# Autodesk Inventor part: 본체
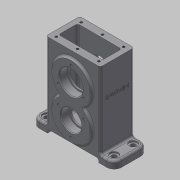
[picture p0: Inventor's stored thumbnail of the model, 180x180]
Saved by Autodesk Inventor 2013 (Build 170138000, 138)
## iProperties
Created: 2020-03
Part Number: 본체
Material: 일반
Document SubType Name: Modeling
Designer: mduedu
Density: 1 g/cm^3
Author: mduedu
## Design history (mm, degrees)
sketch "스케치1"
  geometry: L1 (-56, 0)-(56, 0); L2 (56, 0)-(56, 10); L3 (-56, 10)-(-56, 0); L4 (37, 10)-(37, 114); L5 (37, 114)-(-37, 114); L6 (-37, 114)-(-37, 10); L7 (56, 10)-(37, 10); L8 (-37, 10)-(-56, 10); L9 (0, 0)-(0, 114); 1 further point
  constraints: 18 end point, 5 parallel, 2 midpoint, 2 vertical, 1 coincident, 1 horizontal, 1 perpendicular
  dimensions: "d0" = 112 distance of L1.start L1.end; "d2" = 10 distance of L1.end L2.end; "d3" = 114 distance between parallel lines of L5 L1; "d4" = 74 distance between parallel lines of L4 L6
extrude "돌출1" new body sketch "스케치1" stored distance "d5" = 46; taper "d6" = 0 deg
sketch "스케치2"
  geometry: L1 (56, 0)-(-56, 0) reference; C1 r 26 at (0, 34); C2 r 26 at (0, 79); 1 further point
  constraints: 2 centre point, 2 vertical alignment, 1 equal radius
  dimensions: "d7" = 52 diameter of C2; "d9" = 34 distance from line of C1.centre L1; "d10" = 45 distance of C2.centre C1.centre
extrude "돌출2" join sketch "스케치2" stored distance "d11" = 52; taper "d12" = 0 deg
fillet "모깎기1" dims "d13" = 3
fillet "모깎기2" dims "d14" = 3
fillet "모깎기3" dims "d15" = 10
fillet "모깎기4" dims "d16" = 3
fillet "모깎기5" dims "d17" = 3
sketch "스케치3"
  geometry: L1 (-30, 114)-(30, 114); L2 (30, 114)-(30, 13); L3 (30, 13)-(-30, 13); L4 (-30, 13)-(-30, 114); L5 (-34, 114)-(34, 114) reference; L6 (46, 0)-(-46, 0) reference; 2 further points
  constraints: 8 end point, 2 parallel, 1 collinear, 1 horizontal, 1 midpoint, 1 perpendicular, 1 vertical alignment
  dimensions: "d18" = 60 distance between parallel lines of L2 L4; "d20" = 13 distance between parallel lines of L3 L6
extrude "돌출3" cut sketch "스케치3" stored distance "d21" = 26; taper "d22" = 0 deg
fillet "모깎기6" dims "d23" = 3
fillet "모깎기7" dims "d24" = 3
sketch "스케치4"
  geometry: L1 (-35, 0)-(35, 0); L2 (35, 0)-(35, 5); L3 (35, 5)-(-35, 5); L4 (-35, 5)-(-35, 0); 2 further points
  constraints: 8 end point, 2 parallel, 1 coincident, 1 horizontal, 1 midpoint, 1 perpendicular
  dimensions: "d25" = 70 distance of L1.start L1.end; "d27" = 5 distance of L1.end L2.end
extrude "돌출4" cut sketch "스케치4" stored distance "d28" = 26; taper "d29" = 0 deg
fillet "모깎기8" dims "d30" = 3
sketch "스케치5"
  geometry: A1 r 10 centre (-86, 33) between (-86, 43) and (-96, 33) reference; A2 r 10 centre (-86, 7) between (-96, 7) and (-86, -3) reference; A3 r 10 centre (6, 7) between (6, -3) and (16, 7) reference; A4 r 10 centre (6, 33) between (16, 33) and (6, 43) reference; 5 further points
  constraints: 4 coincident
hole "구멍1" sketch "스케치5" at (-86, 33), (-86, 7), (6, 7), (6, 33) diameter "d31" = 6.6; stored, may be unused: countersink angle "d35" = 90 deg, drill point angle "d37" = 118 deg; dims "d32" = 6, "d33" = 11, "d34" = 2, "d36" = 8
sketch "스케치6"
  geometry: A1 r 26 centre (0, 34) between (-16.403, 54.172) and (16.403, 54.172) reference; A2 r 3 centre (18.296, 56.5) between (16.403, 58.828) and (16.403, 54.172) reference; A3 r 26 centre (0, 79) between (16.403, 58.828) and (-16.403, 58.828) reference; A4 r 3 centre (-18.296, 56.5) between (-16.403, 54.172) and (-16.403, 58.828) reference; 2 further points
  constraints: 1 coincident
hole "구멍2" sketch "스케치6" at (0, 79) diameter "d38" = 28; stored, may be unused: countersink angle "d42" = 90 deg, drill point angle "d44" = 118 deg; dims "d39" = 6, "d40" = 32, "d41" = 11, "d43" = 8
sketch "스케치7"
  geometry: C1 r 16 at (0, 79) reference; A1 r 26 centre (0, 34) between (-16.403, 54.172) and (16.403, 54.172) reference; A2 r 3 centre (18.296, 56.5) between (16.403, 58.828) and (16.403, 54.172) reference; A3 r 26 centre (0, 79) between (16.403, 58.828) and (-16.403, 58.828) reference; A4 r 3 centre (-18.296, 56.5) between (-16.403, 54.172) and (-16.403, 58.828) reference; 2 further points
  constraints: 1 coincident
hole "구멍3" sketch "스케치7" at (0, 34) diameter "d45" = 24; stored, may be unused: countersink angle "d49" = 90 deg, drill point angle "d51" = 118 deg; dims "d46" = 6, "d47" = 28, "d48" = 11, "d50" = 8
sketch "스케치8"
  geometry: C1 r 14 at (0, 34) reference; A1 r 26 centre (0, 34) between (-16.403, 54.172) and (16.403, 54.172) reference; A2 r 3 centre (18.296, 56.5) between (16.403, 58.828) and (16.403, 54.172) reference; A3 r 26 centre (0, 79) between (16.403, 58.828) and (-16.403, 58.828) reference; A4 r 3 centre (-18.296, 56.5) between (-16.403, 54.172) and (-16.403, 58.828) reference; 2 further points
  constraints: 1 coincident
hole "구멍4" sketch "스케치8" at (0, 79) diameter "d52" = 24; stored, may be unused: countersink angle "d56" = 90 deg, drill point angle "d58" = 118 deg; dims "d53" = 6, "d54" = 28, "d55" = 11, "d57" = 8
sketch "스케치9" dims "d59" = 40
  geometry: C1 r 14 at (0, 34) reference; C2 r 16 at (0, 79) reference; A1 r 26 centre (0, 34) between (-16.403, 54.172) and (16.403, 54.172) reference; A2 r 3 centre (18.296, 56.5) between (16.403, 58.828) and (16.403, 54.172) reference; A3 r 26 centre (0, 79) between (16.403, 58.828) and (-16.403, 58.828) reference; A4 r 3 centre (-18.296, 56.5) between (-16.403, 54.172) and (-16.403, 58.828) reference; 3 further points
  constraints: 2 vertical alignment, 1 coincident, 2 other
hole "구멍5" sketch "스케치9" at (0, 99) diameter "d61" = 3.242; stored, may be unused: countersink angle "d65" = 90 deg, drill point angle "d67" = 118 deg; dims "d62" = 8, "d63" = 28, "d64" = 11, "d66" = 10
sketch "스케치10" dims "d71" = 40
  geometry: C1 r 1.621 at (17.321, 69) reference; C2 r 1.621 at (-17.321, 69) reference; C3 r 1.621 at (0, 99) reference; C4 r 14 at (0, 34) reference; C5 r 16 at (0, 79) reference; A1 r 26 centre (0, 34) between (-16.403, 54.172) and (16.403, 54.172) reference; A2 r 3 centre (18.296, 56.5) between (16.403, 58.828) and (16.403, 54.172) reference; A3 r 26 centre (0, 79) between (16.403, 58.828) and (-16.403, 58.828) reference; A4 r 3 centre (-18.296, 56.5) between (-16.403, 54.172) and (-16.403, 58.828) reference; 3 further points
  constraints: 2 vertical alignment, 1 coincident, 2 other
hole "구멍6" sketch "스케치10" at (0, 14) diameter "d72" = 3.242; stored, may be unused: countersink angle "d76" = 90 deg, drill point angle "d78" = 118 deg; dims "d73" = 8, "d74" = 28, "d75" = 11, "d77" = 10
sketch "스케치11"
  geometry: L1 (5, 6)-(63, 6); L2 (63, 6)-(63, 40); L3 (63, 40)-(5, 40); L4 (5, 40)-(5, 6); L5 (5, 6)-(63, 40); L6 (63, 6)-(5, 40); 7 further points
  constraints: 12 end point, 4 coincident, 4 midpoint, 2 parallel, 1 horizontal, 1 perpendicular
  dimensions: "d82" = 58 distance of L3.end L2.end; "d83" = 34 distance of L2.end L1.end
hole "구멍7" sketch "스케치11" at (5, 40), (63, 40), (63, 6), (5, 6), (34, 6), (34, 40) diameter "d84" = 3.242; stored, may be unused: countersink angle "d88" = 90 deg, drill point angle "d90" = 118 deg; dims "d85" = 8, "d86" = 28, "d87" = 11, "d89" = 10
fillet "모깎기9" dims "d91" = 0.3
chamfer "모따기1" distance "d92" = 1; stored, may be unused: second distance "d93" = 2, angle "d94" = 45 deg
sketch "스케치12"
  geometry: 2 further points
  constraints: 1 coincident
hole "구멍8" sketch "스케치12" at (0, -23) diameter "d95" = 4.917; stored, may be unused: countersink angle "d99" = 90 deg, drill point angle "d101" = 118 deg; dims "d96" = 8, "d97" = 12, "d98" = 1, "d100" = 10
sketch "스케치13"
  geometry: L1 (33, -13)-(7, -13) reference; L2 (40, 101)-(0, 101) reference; 3 further points
  constraints: 1 midpoint, 1 vertical alignment, 1 other
  dimensions: "d102" = 40 distance from line of point (20, 61) L2
feature "엠보싱1" sketch "스케치13" dims "d0" = 112, "d2" = 10, "d3" = 114, "d4" = 74, "d13" = 3, "d103" = 0.5, "d104" = 0
node "솔리드1"
mirror "대칭1"
pattern_circular "원형 패턴1" dims angle "d69" = 360 deg
pattern_circular "원형 패턴2" dims angle "d80" = 360 deg
mirror "대칭2"
node "투영된 루프1"
node "투영된 루프2"
node "투영된 루프3"
node "투영된 루프4"
node "투영된 루프5"
